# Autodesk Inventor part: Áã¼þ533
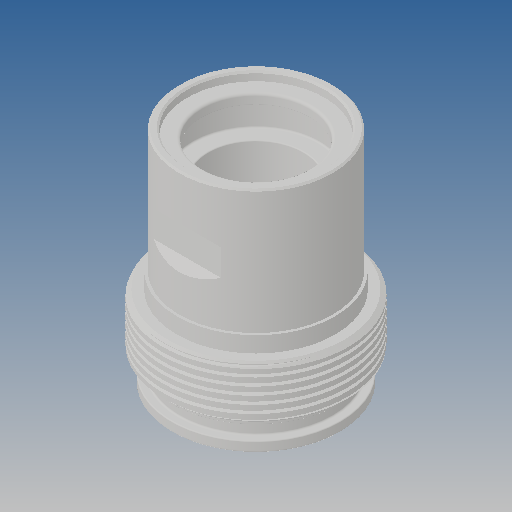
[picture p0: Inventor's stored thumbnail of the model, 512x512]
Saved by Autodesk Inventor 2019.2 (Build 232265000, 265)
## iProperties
Created: 2013-09
Part Number: Áã¼þ533
Material: Ogólny
Document SubType Name: Modeling
Designer: CADENGINEERING4
Density: 1 g/cm^3
Appearance: Domyślna
Author: CADENGINEERING4
Revision Number: ÈÎºÎ
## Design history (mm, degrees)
feature "ÇÐ³ý-À­Éì4"
node "Bryła1"
